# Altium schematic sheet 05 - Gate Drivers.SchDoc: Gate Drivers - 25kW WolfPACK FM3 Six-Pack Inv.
size 431 x 279 mm; Date: 01/2024; DocumentNumber: CRD25DA12N-FMC; Revision: 1.2; SheetNumber: 5; SheetTotal: 8; SheetSize: B
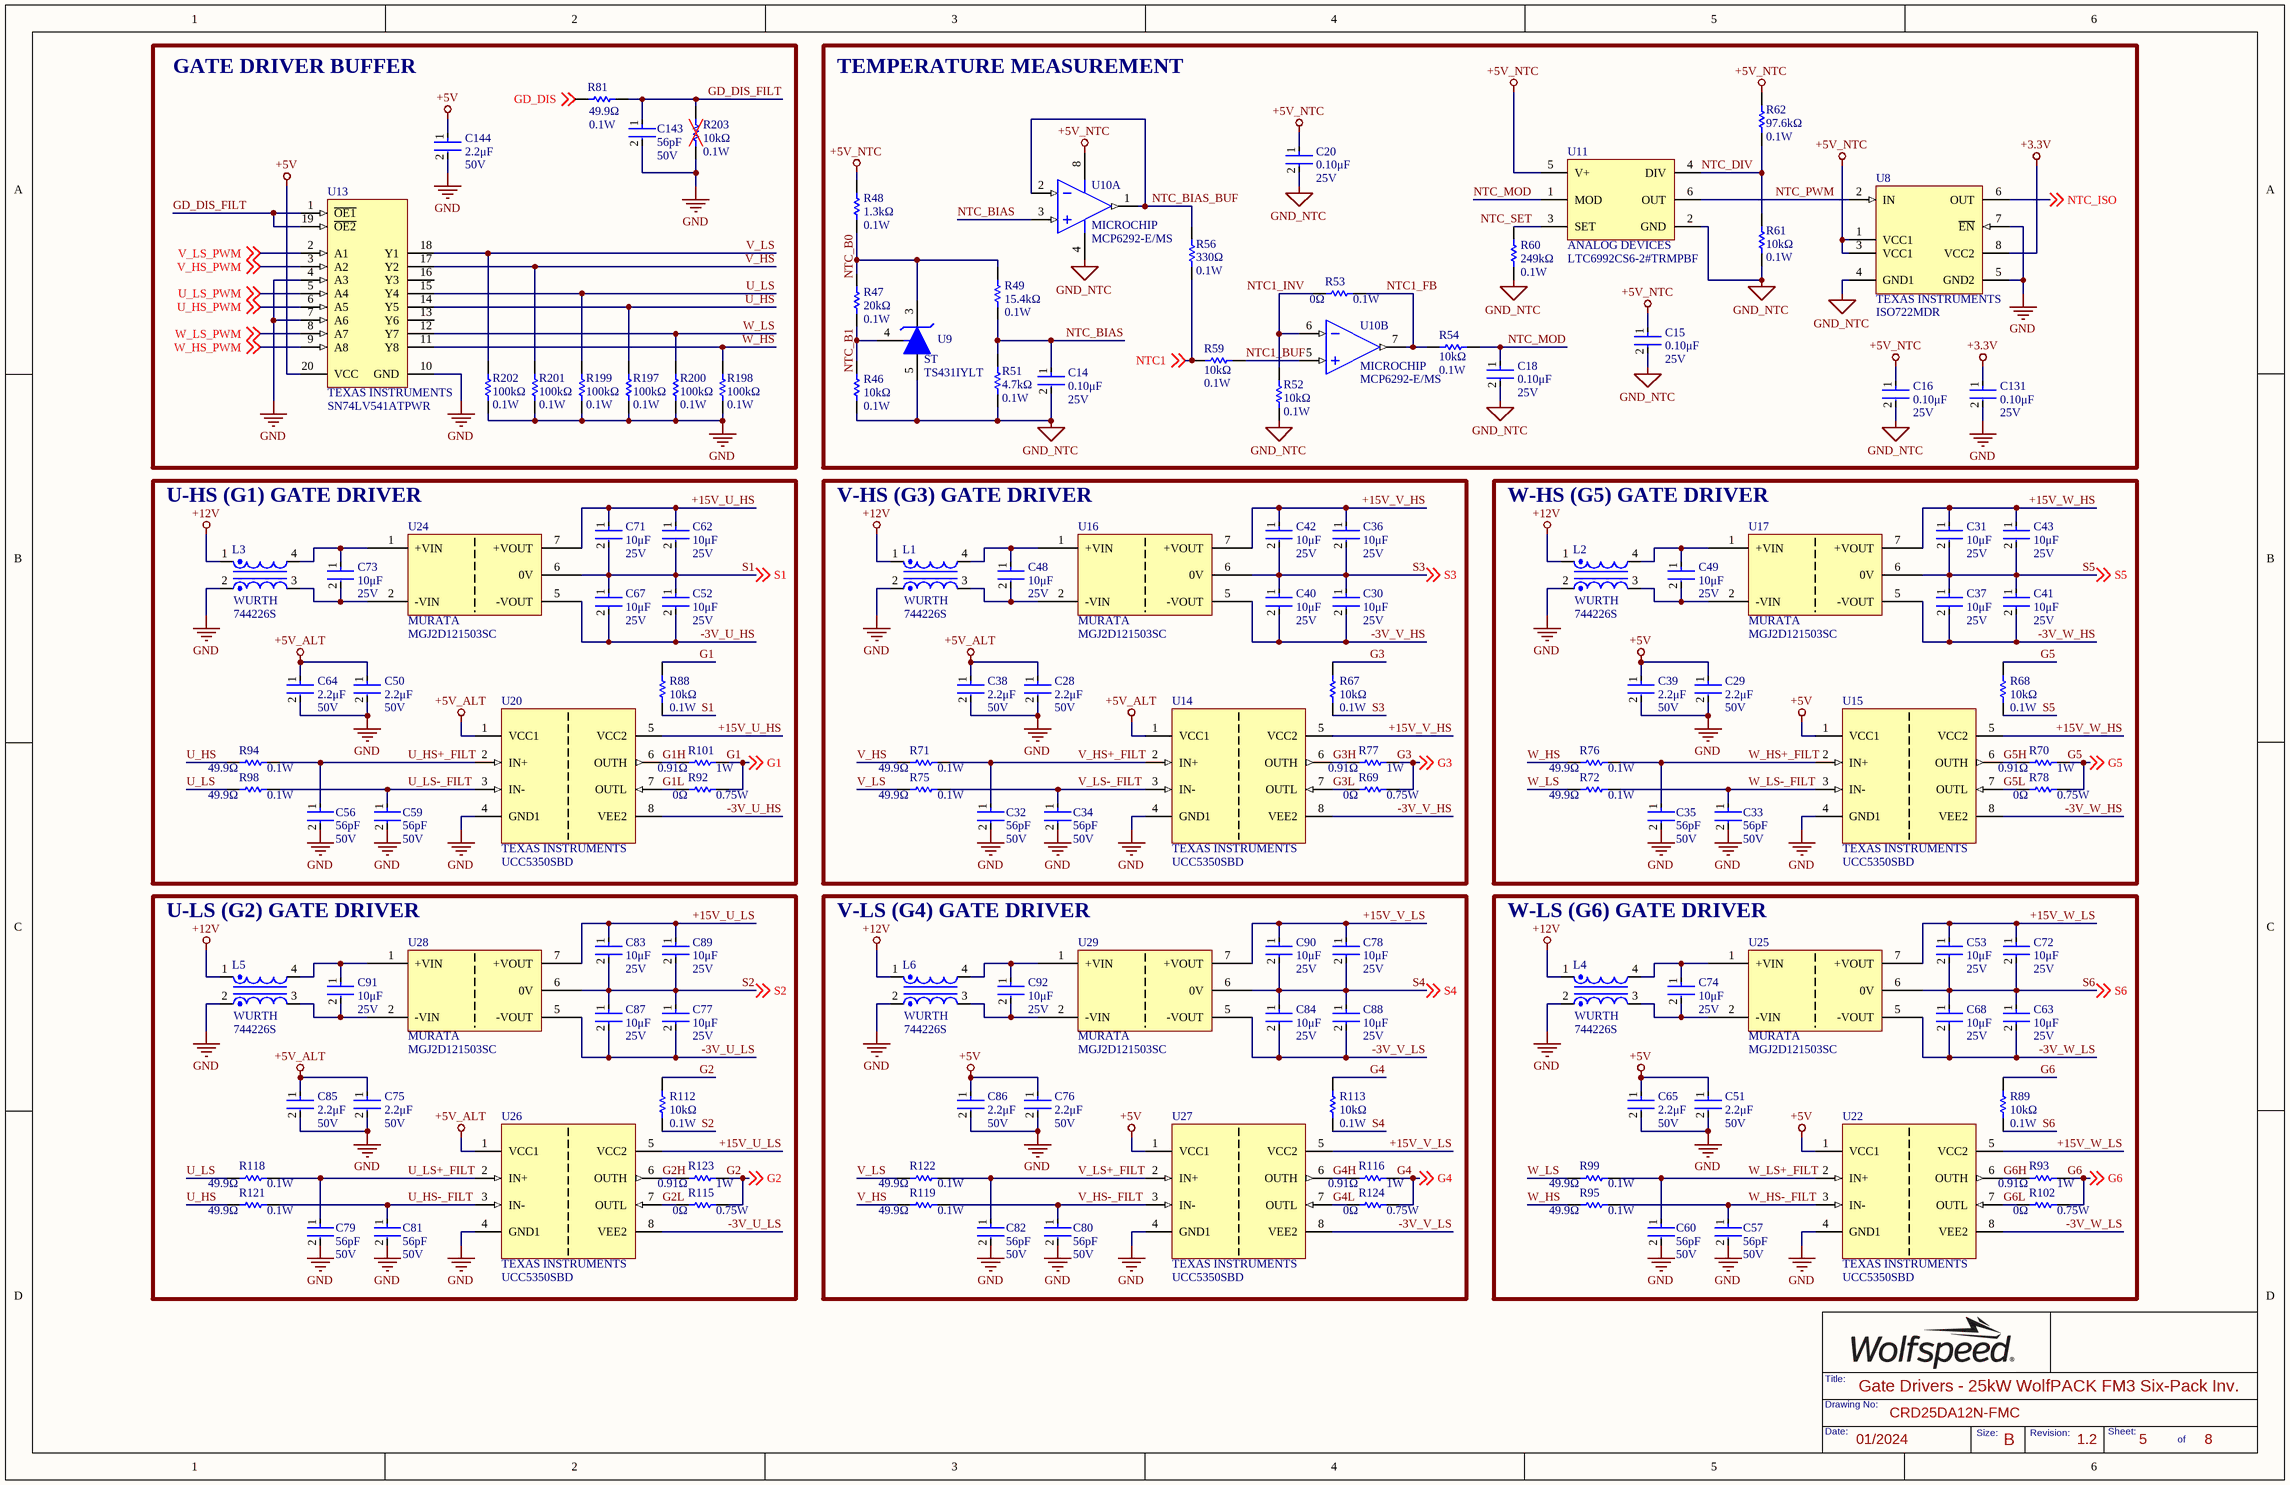
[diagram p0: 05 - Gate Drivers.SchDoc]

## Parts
C14  Voltage Rating: 25V  Capacitance: 0.10μF  [FP-C0603C-CF-IPC_B]  (hidden comment: C0603C104K3RACTU)
C15  Voltage Rating: 25V  Capacitance: 0.10μF  [FP-C0603C-CF-IPC_B]  (hidden comment: C0603C104K3RACTU)
C16  Voltage Rating: 25V  Capacitance: 0.10μF  [FP-C0603C-CF-IPC_B]  (hidden comment: C0603C104K3RACTU)
C18  Voltage Rating: 25V  Capacitance: 0.10μF  [FP-C0603C-CF-IPC_B]  (hidden comment: C0603C104K3RACTU)
C20  Voltage Rating: 25V  Capacitance: 0.10μF  [FP-C0603C-CF-IPC_B]  (hidden comment: C0603C104K3RACTU)
C28  Voltage Rating: 50V  Capacitance: 2.2μF  [FP-C0603C-CF-IPC_B]  (hidden comment: GRT188R61H225ME13D)
C29  Voltage Rating: 50V  Capacitance: 2.2μF  [FP-C0603C-CF-IPC_B]  (hidden comment: GRT188R61H225ME13D)
C30  Voltage Rating: 25V  Capacitance: 10μF  [FP-CL31-IPC_B]  (hidden comment: CL31B106KAHSFNE)
C31  Voltage Rating: 25V  Capacitance: 10μF  [FP-CL31-IPC_B]  (hidden comment: CL31B106KAHSFNE)
C32  Capacitance: 56pF  Voltage Rating: 50V  [FP-C0603C-CF-IPC_B]  (hidden comment: CL10C560JB8NNNC)
C33  Capacitance: 56pF  Voltage Rating: 50V  [FP-C0603C-CF-IPC_B]  (hidden comment: CL10C560JB8NNNC)
C34  Capacitance: 56pF  Voltage Rating: 50V  [FP-C0603C-CF-IPC_B]  (hidden comment: CL10C560JB8NNNC)
C35  Capacitance: 56pF  Voltage Rating: 50V  [FP-C0603C-CF-IPC_B]  (hidden comment: CL10C560JB8NNNC)
C36  Voltage Rating: 25V  Capacitance: 10μF  [FP-CL31-IPC_B]  (hidden comment: CL31B106KAHSFNE)
C37  Voltage Rating: 25V  Capacitance: 10μF  [FP-CL31-IPC_B]  (hidden comment: CL31B106KAHSFNE)
C38  Voltage Rating: 50V  Capacitance: 2.2μF  [FP-C0603C-CF-IPC_B]  (hidden comment: GRT188R61H225ME13D)
C39  Voltage Rating: 50V  Capacitance: 2.2μF  [FP-C0603C-CF-IPC_B]  (hidden comment: GRT188R61H225ME13D)
C40  Voltage Rating: 25V  Capacitance: 10μF  [FP-CL31-IPC_B]  (hidden comment: CL31B106KAHSFNE)
C41  Voltage Rating: 25V  Capacitance: 10μF  [FP-CL31-IPC_B]  (hidden comment: CL31B106KAHSFNE)
C42  Voltage Rating: 25V  Capacitance: 10μF  [FP-CL31-IPC_B]  (hidden comment: CL31B106KAHSFNE)
C43  Voltage Rating: 25V  Capacitance: 10μF  [FP-CL31-IPC_B]  (hidden comment: CL31B106KAHSFNE)
C48  Voltage Rating: 25V  Capacitance: 10μF  [FP-CL31-IPC_B]  (hidden comment: CL31B106KAHSFNE)
C49  Voltage Rating: 25V  Capacitance: 10μF  [FP-CL31-IPC_B]  (hidden comment: CL31B106KAHSFNE)
C50  Voltage Rating: 50V  Capacitance: 2.2μF  [FP-C0603C-CF-IPC_B]  (hidden comment: GRT188R61H225ME13D)
C51  Voltage Rating: 50V  Capacitance: 2.2μF  [FP-C0603C-CF-IPC_B]  (hidden comment: GRT188R61H225ME13D)
C52  Voltage Rating: 25V  Capacitance: 10μF  [FP-CL31-IPC_B]  (hidden comment: CL31B106KAHSFNE)
C53  Voltage Rating: 25V  Capacitance: 10μF  [FP-CL31-IPC_B]  (hidden comment: CL31B106KAHSFNE)
C56  Capacitance: 56pF  Voltage Rating: 50V  [FP-C0603C-CF-IPC_B]  (hidden comment: CL10C560JB8NNNC)
C57  Capacitance: 56pF  Voltage Rating: 50V  [FP-C0603C-CF-IPC_B]  (hidden comment: CL10C560JB8NNNC)
C59  Capacitance: 56pF  Voltage Rating: 50V  [FP-C0603C-CF-IPC_B]  (hidden comment: CL10C560JB8NNNC)
C60  Capacitance: 56pF  Voltage Rating: 50V  [FP-C0603C-CF-IPC_B]  (hidden comment: CL10C560JB8NNNC)
C62  Voltage Rating: 25V  Capacitance: 10μF  [FP-CL31-IPC_B]  (hidden comment: CL31B106KAHSFNE)
C63  Voltage Rating: 25V  Capacitance: 10μF  [FP-CL31-IPC_B]  (hidden comment: CL31B106KAHSFNE)
C64  Voltage Rating: 50V  Capacitance: 2.2μF  [FP-C0603C-CF-IPC_B]  (hidden comment: GRT188R61H225ME13D)
C65  Voltage Rating: 50V  Capacitance: 2.2μF  [FP-C0603C-CF-IPC_B]  (hidden comment: GRT188R61H225ME13D)
C67  Voltage Rating: 25V  Capacitance: 10μF  [FP-CL31-IPC_B]  (hidden comment: CL31B106KAHSFNE)
C68  Voltage Rating: 25V  Capacitance: 10μF  [FP-CL31-IPC_B]  (hidden comment: CL31B106KAHSFNE)
C71  Voltage Rating: 25V  Capacitance: 10μF  [FP-CL31-IPC_B]  (hidden comment: CL31B106KAHSFNE)
C72  Voltage Rating: 25V  Capacitance: 10μF  [FP-CL31-IPC_B]  (hidden comment: CL31B106KAHSFNE)
C73  Voltage Rating: 25V  Capacitance: 10μF  [FP-CL31-IPC_B]  (hidden comment: CL31B106KAHSFNE)
C74  Voltage Rating: 25V  Capacitance: 10μF  [FP-CL31-IPC_B]  (hidden comment: CL31B106KAHSFNE)
C75  Voltage Rating: 50V  Capacitance: 2.2μF  [FP-C0603C-CF-IPC_B]  (hidden comment: GRT188R61H225ME13D)
C76  Voltage Rating: 50V  Capacitance: 2.2μF  [FP-C0603C-CF-IPC_B]  (hidden comment: GRT188R61H225ME13D)
C77  Voltage Rating: 25V  Capacitance: 10μF  [FP-CL31-IPC_B]  (hidden comment: CL31B106KAHSFNE)
C78  Voltage Rating: 25V  Capacitance: 10μF  [FP-CL31-IPC_B]  (hidden comment: CL31B106KAHSFNE)
C79  Capacitance: 56pF  Voltage Rating: 50V  [FP-C0603C-CF-IPC_B]  (hidden comment: CL10C560JB8NNNC)
C80  Capacitance: 56pF  Voltage Rating: 50V  [FP-C0603C-CF-IPC_B]  (hidden comment: CL10C560JB8NNNC)
C81  Capacitance: 56pF  Voltage Rating: 50V  [FP-C0603C-CF-IPC_B]  (hidden comment: CL10C560JB8NNNC)
C82  Capacitance: 56pF  Voltage Rating: 50V  [FP-C0603C-CF-IPC_B]  (hidden comment: CL10C560JB8NNNC)
C83  Voltage Rating: 25V  Capacitance: 10μF  [FP-CL31-IPC_B]  (hidden comment: CL31B106KAHSFNE)
C84  Voltage Rating: 25V  Capacitance: 10μF  [FP-CL31-IPC_B]  (hidden comment: CL31B106KAHSFNE)
C85  Voltage Rating: 50V  Capacitance: 2.2μF  [FP-C0603C-CF-IPC_B]  (hidden comment: GRT188R61H225ME13D)
C86  Voltage Rating: 50V  Capacitance: 2.2μF  [FP-C0603C-CF-IPC_B]  (hidden comment: GRT188R61H225ME13D)
C87  Voltage Rating: 25V  Capacitance: 10μF  [FP-CL31-IPC_B]  (hidden comment: CL31B106KAHSFNE)
C88  Voltage Rating: 25V  Capacitance: 10μF  [FP-CL31-IPC_B]  (hidden comment: CL31B106KAHSFNE)
C89  Voltage Rating: 25V  Capacitance: 10μF  [FP-CL31-IPC_B]  (hidden comment: CL31B106KAHSFNE)
C90  Voltage Rating: 25V  Capacitance: 10μF  [FP-CL31-IPC_B]  (hidden comment: CL31B106KAHSFNE)
C91  Voltage Rating: 25V  Capacitance: 10μF  [FP-CL31-IPC_B]  (hidden comment: CL31B106KAHSFNE)
C92  Voltage Rating: 25V  Capacitance: 10μF  [FP-CL31-IPC_B]  (hidden comment: CL31B106KAHSFNE)
C131  Voltage Rating: 25V  Capacitance: 0.10μF  [FP-C0603C-CF-IPC_B]  (hidden comment: C0603C104K3RACTU)
C143  Capacitance: 56pF  Voltage Rating: 50V  [FP-C0603C-CF-IPC_B]  (hidden comment: CL10C560JB8NNNC)
C144  Voltage Rating: 50V  Capacitance: 2.2μF  [FP-C0603C-CF-IPC_B]  (hidden comment: GRT188R61H225ME13D)
L1  744226S  Manufacturer Print: WURTH  [WE-SL2]
L2  744226S  Manufacturer Print: WURTH  [WE-SL2]
L3  744226S  Manufacturer Print: WURTH  [WE-SL2]
L4  744226S  Manufacturer Print: WURTH  [WE-SL2]
L5  744226S  Manufacturer Print: WURTH  [WE-SL2]
L6  744226S  Manufacturer Print: WURTH  [WE-SL2]
R46  Resistance: 10kΩ  Max Power Dissipation: 0.1W  [FP-MCR03-IPC_B]  (hidden comment: ERJ3EKF1002V)
R47  Resistance: 20kΩ  Power Rating: 0.1W  [FP-MCR03-IPC_B]  (hidden comment: CRCW060320K0FKTA)
R48  Power Rating: 0.1W  Resistance: 1.3kΩ  [FP-MCR03-IPC_B]  (hidden comment: ERA3AEB132V)
R49  Power Rating: 0.1W  Resistance: 15.4kΩ  [FP-MCR03-IPC_B]  (hidden comment: RC1608F1542CS)
R51  Resistance: 4.7kΩ  Power Rating: 0.1W  [FP-MCR03-IPC_B]  (hidden comment: CRCW06034K70FKTA)
R52  Resistance: 10kΩ  Max Power Dissipation: 0.1W  [FP-MCR03-IPC_B]  (hidden comment: ERJ3EKF1002V)
R53  Resistance: 0Ω  Power Rating: 0.1W  [FP-MCR03-IPC_B]  (hidden comment: CRCW06030000Z0EB)
R54  Resistance: 10kΩ  Max Power Dissipation: 0.1W  [FP-MCR03-IPC_B]  (hidden comment: ERJ3EKF1002V)
R56  Resistance: 330Ω  Power Rating: 0.1W  [FP-MCR03-IPC_B]  (hidden comment: RC0603FR-13330RL)
R59  Resistance: 10kΩ  Max Power Dissipation: 0.1W  [FP-MCR03-IPC_B]  (hidden comment: ERJ3EKF1002V)
R60  Max Power Dissipation: 0.1W  Resistance: 249kΩ  [FP-MCR03-IPC_B]  (hidden comment: RMCF0603FT249K)
R61  Resistance: 10kΩ  Max Power Dissipation: 0.1W  [FP-MCR03-IPC_B]  (hidden comment: ERJ3EKF1002V)
R62  Resistance: 97.6kΩ  Max Power Dissipation: 0.1W  [FP-MCR03-IPC_B]  (hidden comment: ERJ-3EKF9762V)
R67  Resistance: 10kΩ  Max Power Dissipation: 0.1W  [FP-MCR03-IPC_B]  (hidden comment: ERJ3EKF1002V)
R68  Resistance: 10kΩ  Max Power Dissipation: 0.1W  [FP-MCR03-IPC_B]  (hidden comment: ERJ3EKF1002V)
R69  value 0Ω  Power Rating: 0.75W  [RESC3125X70X40NL20T20]  (hidden comment: CRCW12100000Z0EAHP)
R70  value 0.91Ω  Power: 1W  [RESC3125X70X40NL20T20]  (hidden comment: RCWE1210R910FKEA)
R71  Resistance: 49.9Ω  Power Rating: 0.1W  [FP-MCR03-IPC_B]  (hidden comment: ERJ-3EKF49R9V)
R72  Resistance: 49.9Ω  Power Rating: 0.1W  [FP-MCR03-IPC_B]  (hidden comment: ERJ-3EKF49R9V)
R75  Resistance: 49.9Ω  Power Rating: 0.1W  [FP-MCR03-IPC_B]  (hidden comment: ERJ-3EKF49R9V)
R76  Resistance: 49.9Ω  Power Rating: 0.1W  [FP-MCR03-IPC_B]  (hidden comment: ERJ-3EKF49R9V)
R77  value 0.91Ω  Power: 1W  [RESC3125X70X40NL20T20]  (hidden comment: RCWE1210R910FKEA)
R78  value 0Ω  Power Rating: 0.75W  [RESC3125X70X40NL20T20]  (hidden comment: CRCW12100000Z0EAHP)
R81  Resistance: 49.9Ω  Power Rating: 0.1W  [FP-MCR03-IPC_B]  (hidden comment: ERJ-3EKF49R9V)
R88  Resistance: 10kΩ  Max Power Dissipation: 0.1W  [FP-MCR03-IPC_B]  (hidden comment: ERJ3EKF1002V)
R89  Resistance: 10kΩ  Max Power Dissipation: 0.1W  [FP-MCR03-IPC_B]  (hidden comment: ERJ3EKF1002V)
R92  value 0Ω  Power Rating: 0.75W  [RESC3125X70X40NL20T20]  (hidden comment: CRCW12100000Z0EAHP)
R93  value 0.91Ω  Power: 1W  [RESC3125X70X40NL20T20]  (hidden comment: RCWE1210R910FKEA)
R94  Resistance: 49.9Ω  Power Rating: 0.1W  [FP-MCR03-IPC_B]  (hidden comment: ERJ-3EKF49R9V)
R95  Resistance: 49.9Ω  Power Rating: 0.1W  [FP-MCR03-IPC_B]  (hidden comment: ERJ-3EKF49R9V)
R98  Resistance: 49.9Ω  Power Rating: 0.1W  [FP-MCR03-IPC_B]  (hidden comment: ERJ-3EKF49R9V)
R99  Resistance: 49.9Ω  Power Rating: 0.1W  [FP-MCR03-IPC_B]  (hidden comment: ERJ-3EKF49R9V)
R101  value 0.91Ω  Power: 1W  [RESC3125X70X40NL20T20]  (hidden comment: RCWE1210R910FKEA)
R102  value 0Ω  Power Rating: 0.75W  [RESC3125X70X40NL20T20]  (hidden comment: CRCW12100000Z0EAHP)
R112  Resistance: 10kΩ  Max Power Dissipation: 0.1W  [FP-MCR03-IPC_B]  (hidden comment: ERJ3EKF1002V)
R113  Resistance: 10kΩ  Max Power Dissipation: 0.1W  [FP-MCR03-IPC_B]  (hidden comment: ERJ3EKF1002V)
R115  value 0Ω  Power Rating: 0.75W  [RESC3125X70X40NL20T20]  (hidden comment: CRCW12100000Z0EAHP)
R116  value 0.91Ω  Power: 1W  [RESC3125X70X40NL20T20]  (hidden comment: RCWE1210R910FKEA)
R118  Resistance: 49.9Ω  Power Rating: 0.1W  [FP-MCR03-IPC_B]  (hidden comment: ERJ-3EKF49R9V)
R119  Resistance: 49.9Ω  Power Rating: 0.1W  [FP-MCR03-IPC_B]  (hidden comment: ERJ-3EKF49R9V)
R121  Resistance: 49.9Ω  Power Rating: 0.1W  [FP-MCR03-IPC_B]  (hidden comment: ERJ-3EKF49R9V)
R122  Resistance: 49.9Ω  Power Rating: 0.1W  [FP-MCR03-IPC_B]  (hidden comment: ERJ-3EKF49R9V)
R123  value 0.91Ω  Power: 1W  [RESC3125X70X40NL20T20]  (hidden comment: RCWE1210R910FKEA)
R124  value 0Ω  Power Rating: 0.75W  [RESC3125X70X40NL20T20]  (hidden comment: CRCW12100000Z0EAHP)
R197  Resistance: 100kΩ  Power Rating: 0.1W  [FP-MCR03-IPC_B]  (hidden comment: RC0603FR-07100KL)
R198  Resistance: 100kΩ  Power Rating: 0.1W  [FP-MCR03-IPC_B]  (hidden comment: RC0603FR-07100KL)
R199  Resistance: 100kΩ  Power Rating: 0.1W  [FP-MCR03-IPC_B]  (hidden comment: RC0603FR-07100KL)
R200  Resistance: 100kΩ  Power Rating: 0.1W  [FP-MCR03-IPC_B]  (hidden comment: RC0603FR-07100KL)
R201  Resistance: 100kΩ  Power Rating: 0.1W  [FP-MCR03-IPC_B]  (hidden comment: RC0603FR-07100KL)
R202  Resistance: 100kΩ  Power Rating: 0.1W  [FP-MCR03-IPC_B]  (hidden comment: RC0603FR-07100KL)
R203  Resistance: 10kΩ  Max Power Dissipation: 0.1W  [FP-MCR03-IPC_B]  (hidden comment: ERJ3EKF1002V)
U8  ISO722MDR  Manufacturer: TEXAS INSTRUMENTS  [D0008B_L]
U9  TS431IYLT  Manufacturer Print: ST  [SOT95P280X145-5N]
U10  MCP6292-E/MS  Manufacturer Print: MICROCHIP  [MSOP-MS8_L]  (parts A,B of 2)
U11  LTC6992CS6-2#TRMPBF  MANUFACTURER PRINT: ANALOG DEVICES  [SOT95P280X100-6N]
U13  Manufacturer: TEXAS INSTRUMENTS  [PW0020A_L]  (hidden comment: SN74LV541ATPWR)
U14  UCC5350SBD  Manufacturer Print: TEXAS INSTRUMENTS  [D0008B_HV]
U15  UCC5350SBD  Manufacturer Print: TEXAS INSTRUMENTS  [D0008B_HV]
U16  MGJ2D121503SC  Manufacturer Print: MURATA  [MGJ2D121509SC]
U17  MGJ2D121503SC  Manufacturer Print: MURATA  [MGJ2D121509SC]
U20  UCC5350SBD  Manufacturer Print: TEXAS INSTRUMENTS  [D0008B_HV]
U22  UCC5350SBD  Manufacturer Print: TEXAS INSTRUMENTS  [D0008B_HV]
U24  MGJ2D121503SC  Manufacturer Print: MURATA  [MGJ2D121509SC]
U25  MGJ2D121503SC  Manufacturer Print: MURATA  [MGJ2D121509SC]
U26  UCC5350SBD  Manufacturer Print: TEXAS INSTRUMENTS  [D0008B_HV]
U27  UCC5350SBD  Manufacturer Print: TEXAS INSTRUMENTS  [D0008B_HV]
U28  MGJ2D121503SC  Manufacturer Print: MURATA  [MGJ2D121509SC]
U29  MGJ2D121503SC  Manufacturer Print: MURATA  [MGJ2D121509SC]

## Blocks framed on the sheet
GATE DRIVER BUFFER: C143 C144 R81 R197-R203 U13
TEMPERATURE MEASUREMENT: C14-C16 C18 C20 C131 R46-R49 R51-R54 R56 R59-R62 U8-U11
U-HS (G1) GATE DRIVER: C50 C52 C56 C59 C62 C64 C67 C71 C73 L3 R88 R92 R94 R98 R101 U20 U24
V-HS (G3) GATE DRIVER: C28 C30 C32 C34 C36 C38 C40 C42 C48 L1 R67 R69 R71 R75 R77 U14 U16
W-HS (G5) GATE DRIVER: C29 C31 C33 C35 C37 C39 C41 C43 C49 L2 R68 R70 R72 R76 R78 U15 U17
U-LS (G2) GATE DRIVER: C75 C77 C79 C81 C83 C85 C87 C89 C91 L5 R112 R115 R118 R121 R123 U26 U28
V-LS (G4) GATE DRIVER: C76 C78 C80 C82 C84 C86 C88 C90 C92 L6 R113 R116 R119 R122 R124 U27 U29
W-LS (G6) GATE DRIVER: C51 C53 C57 C60 C63 C65 C68 C72 C74 L4 R89 R93 R95 R99 R102 U22 U25

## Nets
+3.3V: C131.1 U8.8(VCC2)
+5V: C29.1 C39.1 C51.1 C65.1 C76.1 C86.1 C144.1 U13.20(VCC) U15.1(VCC1) U22.1(VCC1) U27.1(VCC1)
+5V_ALT: C28.1 C38.1 C50.1 C64.1 C75.1 C85.1 U14.1(VCC1) U20.1(VCC1) U26.1(VCC1)
+5V_NTC: C15.1 C16.1 C20.1 R48.2 R62.2 U8.1(VCC1) U8.3(VCC1) U10.8(VDD) U11.5(V+)
+12V: L1.1 L2.1 L3.1 L4.1 L5.1 L6.1
GND: C28.2 C29.2 C32.2 C33.2 C34.2 C35.2 C38.2 C39.2 C50.2 C51.2 C56.2 C57.2 C59.2 C60.2 C64.2 C65.2 C75.2 C76.2 C79.2 C80.2 C81.2 C82.2 C85.2 C86.2 C131.2 C143.2 C144.2 L1.2 L2.2 L3.2 L4.2 L5.2 L6.2 R197.1 R198.1 R199.1 R200.1 R201.1 R202.1 R203.1 U8.5(GND2) U8.7(~{EN}) U13.4(A3) U13.7(A6) U13.10(GND) U14.4(GND1) U15.4(GND1) U20.4(GND1) U22.4(GND1) U26.4(GND1) U27.4(GND1)
GND_NTC: C14.2 C15.2 C16.2 C18.2 C20.2 R46.1 R51.1 R52.1 R60.1 R61.1 U8.4(GND1) U9.5 U10.4(VSS) U11.2(GND)
+15V_U_HS: C62.1 C71.1 U20.5(VCC2) U24.7(+VOUT)
+15V_U_LS: C83.1 C89.1 U26.5(VCC2) U28.7(+VOUT)
+15V_V_HS: C36.1 C42.1 U14.5(VCC2) U16.7(+VOUT)
+15V_V_LS: C78.1 C90.1 U27.5(VCC2) U29.7(+VOUT)
+15V_W_HS: C31.1 C43.1 U15.5(VCC2) U17.7(+VOUT)
+15V_W_LS: C53.1 C72.1 U22.5(VCC2) U25.7(+VOUT)
-3V_U_HS: C52.2 C67.2 U20.8(VEE2) U24.5(-VOUT)
-3V_U_LS: C77.2 C87.2 U26.8(VEE2) U28.5(-VOUT)
-3V_V_HS: C30.2 C40.2 U14.8(VEE2) U16.5(-VOUT)
-3V_V_LS: C84.2 C88.2 U27.8(VEE2) U29.5(-VOUT)
-3V_W_HS: C37.2 C41.2 U15.8(VEE2) U17.5(-VOUT)
-3V_W_LS: C63.2 C68.2 U22.8(VEE2) U25.5(-VOUT)
G1: R88.2 R92.2 R101.2 ; off-sheet G1
G1H: R101.1 U20.6(OUTH)
G1L: R92.1 U20.7(OUTL)
G2: R112.2 R115.2 R123.2 ; off-sheet G2
G2H: R123.1 U26.6(OUTH)
G2L: R115.1 U26.7(OUTL)
G3: R67.2 R69.2 R77.2 ; off-sheet G3
G3H: R77.1 U14.6(OUTH)
G3L: R69.1 U14.7(OUTL)
G4: R113.2 R116.2 R124.2 ; off-sheet G4
G4H: R116.1 U27.6(OUTH)
G4L: R124.1 U27.7(OUTL)
G5: R68.2 R70.2 R78.2 ; off-sheet G5
G5H: R70.1 U15.6(OUTH)
G5L: R78.1 U15.7(OUTL)
G6: R89.2 R93.2 R102.2 ; off-sheet G6
G6H: R93.1 U22.6(OUTH)
G6L: R102.1 U22.7(OUTL)
GD_DIS: R81.1 ; off-sheet GD_DIS
GD_DIS_FILT: C143.1 R81.2 R203.2 U13.1(~{OE1}) U13.19(~{OE2})
NTC1: R56.1 R59.2 ; off-sheet NTC1
NTC1_BUF: R59.1 U10.5(VINB+)
NTC1_FB: R53.2 R54.2 U10.7(VOUTB)
NTC1_INV: R52.2 R53.1 U10.6(VINB-)
NTC_B0: R47.2 R48.1 R49.2 U9.3
NTC_B1: R46.2 R47.1 U9.4
NTC_BIAS: C14.1 R49.1 R51.2 U10.3(VINA+)
NTC_BIAS_BUF: R56.2 U10.1(VOUTA) U10.2(VINA-)
NTC_DIV: R61.2 R62.1 U11.4(DIV)
NTC_ISO: U8.6(OUT) ; off-sheet NTC_ISO
NTC_MOD: C18.1 R54.1 U11.1(MOD)
NTC_PWM: U8.2(IN) U11.6(OUT)
NTC_SET: R60.2 U11.3(SET)
S1: C52.1 C62.2 C67.1 C71.2 R88.1 U24.6(0V) ; off-sheet S1
S2: C77.1 C83.2 C87.1 C89.2 R112.1 U28.6(0V) ; off-sheet S2
S3: C30.1 C36.2 C40.1 C42.2 R67.1 U16.6(0V) ; off-sheet S3
S4: C78.2 C84.1 C88.1 C90.2 R113.1 U29.6(0V) ; off-sheet S4
S5: C31.2 C37.1 C41.1 C43.2 R68.1 U17.6(0V) ; off-sheet S5
S6: C53.2 C63.1 C68.1 C72.2 R89.1 U25.6(0V) ; off-sheet S6
U_HS: R94.1 R121.1 R197.2 U13.14(Y5)
U_HS+_FILT: C56.1 R94.2 U20.2(IN+)
U_HS-_FILT: C81.1 R121.2 U26.3(IN-)
U_HS_PWM: U13.6(A5) ; off-sheet U_HS_PWM
U_LS: R98.1 R118.1 R199.2 U13.15(Y4)
U_LS+_FILT: C79.1 R118.2 U26.2(IN+)
U_LS-_FILT: C59.1 R98.2 U20.3(IN-)
U_LS_PWM: U13.5(A4) ; off-sheet U_LS_PWM
V_HS: R71.1 R119.1 R201.2 U13.17(Y2)
V_HS+_FILT: C32.1 R71.2 U14.2(IN+)
V_HS-_FILT: C80.1 R119.2 U27.3(IN-)
V_HS_PWM: U13.3(A2) ; off-sheet V_HS_PWM
V_LS: R75.1 R122.1 R202.2 U13.18(Y1)
V_LS+_FILT: C82.1 R122.2 U27.2(IN+)
V_LS-_FILT: C34.1 R75.2 U14.3(IN-)
V_LS_PWM: U13.2(A1) ; off-sheet V_LS_PWM
W_HS: R76.1 R95.1 R198.2 U13.11(Y8)
W_HS+_FILT: C35.1 R76.2 U15.2(IN+)
W_HS-_FILT: C57.1 R95.2 U22.3(IN-)
W_HS_PWM: U13.9(A8) ; off-sheet W_HS_PWM
W_LS: R72.1 R99.1 R200.2 U13.12(Y7)
W_LS+_FILT: C60.1 R99.2 U22.2(IN+)
W_LS-_FILT: C33.1 R72.2 U15.3(IN-)
W_LS_PWM: U13.8(A7) ; off-sheet W_LS_PWM
NetC48_1: C48.1 L1.4 U16.1(+VIN)
NetC48_2: C48.2 L1.3 U16.2(-VIN)
NetC49_1: C49.1 L2.4 U17.1(+VIN)
NetC49_2: C49.2 L2.3 U17.2(-VIN)
NetC73_1: C73.1 L3.4 U24.1(+VIN)
NetC73_2: C73.2 L3.3 U24.2(-VIN)
NetC74_1: C74.1 L4.4 U25.1(+VIN)
NetC74_2: C74.2 L4.3 U25.2(-VIN)
NetC91_1: C91.1 L5.4 U28.1(+VIN)
NetC91_2: C91.2 L5.3 U28.2(-VIN)
NetC92_1: C92.1 L6.4 U29.1(+VIN)
NetC92_2: C92.2 L6.3 U29.2(-VIN)

Not connected (* = marked no-connect by the designer): U13 13(Y6) 16(Y3)

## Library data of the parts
C14-C16 C18 C20 C131 = CMP-2006-03057-2: CAP CER 0.1UF 25V X7R 0603; Manufacturer: KEMET; Value: 0.10μF; Material: Ceramic; Tolerance: 0.1; Temperature Coefficient: 30ppm/°C; Automotive Grade: Grade 1
C28 C29 C38 C39 C50 C51 C64 C65 C75 C76 C85 C86 C144 = GRT188R61H225ME13D: CAP CER 2.2UF 50V X5R 0603; Manufacturer: MURATA; Tolerance: 20%; Value: 2.2μF
C30 C31 C36 C37 C40-C43 C48 C49 C52 C53 C62 C63 C67 C68 C71-C74 C77 C78 C83 C84 C87-C92 = CMP-13271-001434-1: CAP CER 10UF 25V X7R 1206; Manufacturer: SAMSUNG; Tolerance: 10%; Value: 10μF
C32-C35 C56 C57 C59 C60 C79-C82 C143 = CL10C560JB8NNNC: CAP CER 56PF 50V C0G/NP0 0603; Manufacturer: SAMSUNG; Material: Ceramic; Tolerance: 5%; Dielectric: C0G; Temperature Coefficient: 30ppm/°C
L1-L6 = 744226S: CMC 10UH 1.6A 2LN 920 OHM SMD; Manufacturer: WURTH ELECTRONIK; Tolerance: 30%; Voltage Rating: 80V; Resistance: 80mR; Impedance: 920R; Number of Lines: 2; Test Frequency: 1kHz; Value: 10μH
R46 R52 R54 R59 R61 R67 R68 R88 R89 R112 R113 R203 = ERJ3EKF1002V: RES SMD 10K OHM 1% 1/10W 0603; Manufacturer: PANASONIC; Manufacturer Part Number: ERJ-3EKF1002V; Temperature Coefficient: 100ppm/°C; Power Rating: 100mW; Voltage Rating: 75V; Value: 10kΩ
R47 = CRCW060320K0FKTA: RES SMD 20K OHM 1% 1/10W 0603; Manufacturer: VISHAY DALE; Temperature Coefficient: 100ppm/°C; Voltage Rating: 75V; Max Power Dissipation: 100mW; Value: 20kΩ
R48 = ERA3AEB132V: RES SMD 1.3K OHM 0.1% 1/10W 0603; Manufacturer: PANASONIC; Manufacturer Part Number: ERA-3AEB132V; Temperature Coefficient: 25ppm/°C; Voltage Rating: 75V; Max Power Dissipation: 100mW; Value: 1.3kΩ
R49 = RC1608F1542CS: RES SMD 15.4K OHM 1% 1/10W 0603; Manufacturer: SAMSUNG; Max Power Dissipation: 100mW; Temperature Coefficient: 100ppm/°C; Voltage Rating (DC): 50V; Value: 15.4kΩ
R51 = CRCW06034K70FKTA: RES SMD 4.7K OHM 1% 1/10W 0603; Manufacturer: VISHAY DALE; Voltage Rating: 75V; Max Power Dissipation: 100mW; Temperature Coefficient: 100ppm/°C; Value: 4.7kΩ
R53 = CRCW06030000Z0EB: RES SMD 0 OHM JUMPER 1/10W 0603; Manufacturer: VISHAY DALE; Manufacturer Part Number: CRCW06030000Z0EBC; Max Power Dissipation: 100mW; Voltage Rating: 75V; Tolerance: 1%; Temperature Coefficient: 100ppm/°C; Value: 0Ω
R56 = RC0603FR-13330RL: RES 330 OHM 1% 1/10W 0603; Manufacturer: YAGEO; Voltage Rating: 50V; Temperature Coefficient: 100ppm/°C; Value: 330Ω
R60 = RMCF0603FT249K: RES 249K OHM 1% 1/10W 0603; Manufacturer: STACKPOLE; Temperature Coefficient: 100ppm/°C; Value: 249kΩ
R62 = ERJ-3EKF9762V: RES SMD 97.6K OHM 1% 1/10W 0603; Manufacturer: PANASONIC; Temperature Coefficient: 100ppm/°C; Voltage Rating: 75V; Power Rating: 100mW; Voltage Rating (DC): 50V; Value: 97.6kΩ
R69 R78 R92 R102 R115 R124 = CRCW12100000Z0EAHP: RES SMD 0 OHM JUMPER 3/4W 1210; Manufacturer: VISHAY DALE; Max Power Dissipation: 750mW
R70 R77 R93 R101 R116 R123 = CMP-2005-02198-1: RES 0.91 OHM 1% 1W 1210; Manufacturer: VISHAY DALE
R71 R72 R75 R76 R81 R94 R95 R98 R99 R118 R119 R121 R122 = ERJ-3EKF49R9V: RES SMD 49.9 OHM 1% 1/10W 0603; Manufacturer: PANASONIC; Temperature Coefficient: 100ppm/°C; Voltage Rating: 75V; Max Power Dissipation: 100mW; Voltage Rating (DC): 50V; Working Voltage: 6V; Value: 49.9Ω
R197-R202 = RC0603FR-07100KL: RES 100K OHM 1% 1/10W 0603; Manufacturer: YAGEO; Temperature Coefficient: 100ppm/°C; Voltage Rating: 50V; Working Voltage: 75V; Max Power Dissipation: 100mW; Value: 100kΩ
U8 = CMP-0328-00055-4: DGTL ISO 2500VRMS 1CH GP 8SOIC; TTL/CMOS Input Threshold: CMOS; Prop Delay(Max)(ns): 16; Input Noise Filter: None; Insulation Rating(VRMS): 2500; Datarate(Mbps): 150; Eco-Plan: Green (RoHS & no Sb/Br); Rating: Catalog; Supply Voltage(s)(V): 3.3, 5; SubFamily: Isolator; Thermal Shutdown: No
U9 = TS431IYLT: IC VREF SHUNT ADJ 2% SOT23-5; Manufacturer: STMICROELECTRONICS; Output Voltage: 6V; Max Input Voltage: 10V; Max Output Current: 30mA; Reference Type: Shunt,Adjustable; Number of Channels: 1; Temperature Coefficient: 100ppm/°C; Cathode Current: 60uA; Output Type: Adjustable; Min Output Voltage: 1.24V
U10 = MCP6292-E/MS: IC OPAMP GP 2 CIRCUIT 8MSOP; Number of Channels: 2; Max Supply Voltage: 5.5V; Unity Gain Bandwidth Product: 10MHz; Slew Rate: 7V/µs; Common Mode Rejection Ratio: 70dB; Min Supply Voltage: 2.4V; Voltage Gain: 110dB; Output Current: 25mA; Nominal Supply Current: 1mA; Input Bias Current: 1pA; Input Offset Voltage (Vos): 3mV; Amplifier Type: GENERAL PURPOSE; Input Offset Voltage-Max: 5mV
U11 = LTC6992CS6-2#TRMPBF: IC OSC SILICON PROG TSOT23-6; Frequency: 3.81Hz; Min Supply Voltage: 2.25V; Max Supply Voltage: 5.5V; Number of Timers/Counters: 1; Operating Supply Current: 365uA
U13 = CMP-0440-01163-3: IC BUF NON-INVERT 5.5V 20TSSOP; Bits(#): 8; Voltage(Nom)(V): 5; ICC @ Nom Voltage(Max)(mA): 0.02; VCC(Max)(V): 5.5; Output Type: CMOS; Rating: Catalog; Input Type: TTL; VCC(Min)(V): 4.5; F @ Nom Voltage(Max)(Mhz): 110; tpd @ Nom Voltage(Max)(ns): 7.9
U14 U15 U20 U22 U26 U27 = UCC5350SBD: 5A/5A, 3-KVRMS SINGLE-CHANNEL IS; Class: U; Working Voltage: 990V; Number of Channels: 1
U16 U17 U24 U25 U28 U29 = MGJ2D121503SC: DC DC CONVERTER 15V -3V 1.7W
